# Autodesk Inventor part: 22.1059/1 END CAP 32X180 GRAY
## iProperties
Created: 2007-01
Part Number: 22.1059/1 END CAP 32X180 GRAY
Document SubType Name: Modeling
Designer: Andy Moles
Material: ABS Plastic
Density: 1.06 g/cm^3
Author: Andy Moles
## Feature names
1. Extrusion1
2. Fillet1
3. Fillet2
4. Extrusion2
5. Fillet3
